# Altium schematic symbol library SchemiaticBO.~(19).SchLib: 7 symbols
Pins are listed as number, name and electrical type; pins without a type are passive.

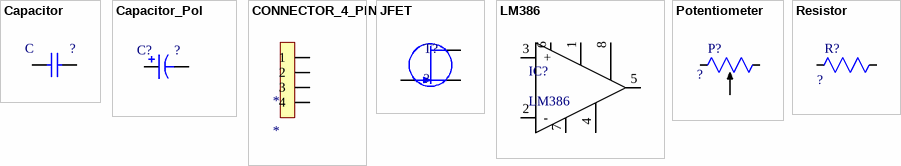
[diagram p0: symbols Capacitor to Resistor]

## Capacitor
designator C  (value not drawn)
footprint SMD_0603_BO
footprint SMD_1206_BO
pins: 1, 2

## Capacitor_Pol
designator C?  (value not drawn)
footprint PANASONIC_B_BO
footprint PANASONIC_C_BO
footprint PANASONIC_D8_BO
pins: 1, 2

## CONNECTOR_4_PIN
designator *
footprint Connector double
pins: 1, 2, 3, 4

## JFET
designator T?, comment ?
footprint SOT23_BO
pins: 1 D, 2 S, 3 G

## LM386
designator IC?
footprint SO8_BO
pins: 1, 2 -, 3 +, 4, 5, 6, 7, 8

## Potentiometer
designator P?  (value not drawn)
footprint POT_1801-J_BO
pins: 1, 2, 3

## Resistor
designator R?  (value not drawn)
footprint SMD_1206_BO
pins: 1 OUT, 2 OUT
